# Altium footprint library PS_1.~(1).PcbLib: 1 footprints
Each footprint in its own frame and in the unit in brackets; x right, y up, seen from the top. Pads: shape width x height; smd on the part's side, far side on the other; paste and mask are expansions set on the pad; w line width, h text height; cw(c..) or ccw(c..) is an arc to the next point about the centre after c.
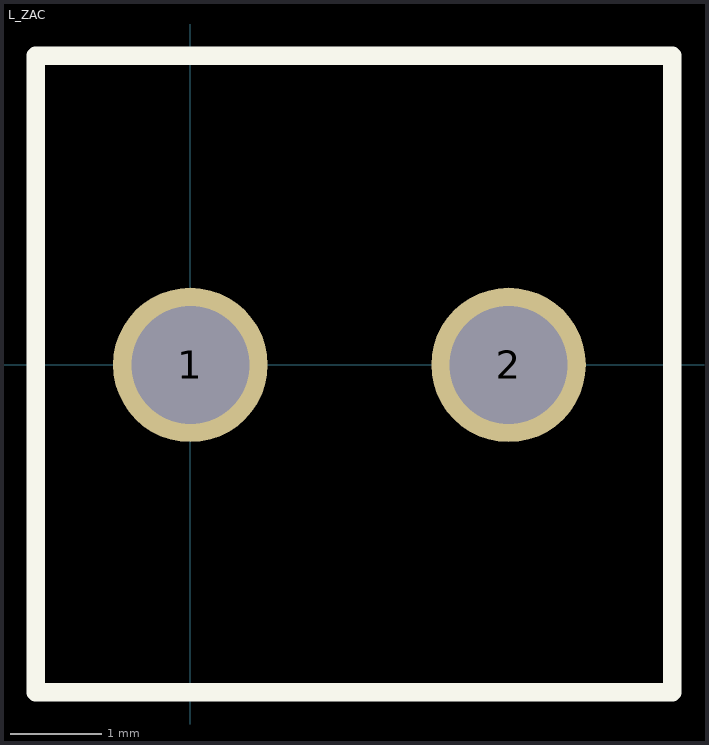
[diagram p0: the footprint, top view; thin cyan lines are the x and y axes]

## L_ZAC [mm]
pads (2):
  round 1.7 hole 1.3: 1(0,0) 2(3.5,0)
Top Overlay:
  lines w0.2: -1.7,-3.6 5.3,-3.6 5.3,3.4 -1.7,3.4 -1.7,-3.6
